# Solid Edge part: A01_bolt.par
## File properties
Author: mokuno
Template: metric.par
Last saved by: edge
Revision: 32
Application: Solid Edge
Material: Copper
File Size: 0
Number of Sheets: 0
Number of Objects: 0
非切断部品: False
文書内容のタイプ: 0
Density: 8906
Accuracy: 0.99
Document Number: MP-101
Revision: 1
Project Name: Trolley Wheel Assembly
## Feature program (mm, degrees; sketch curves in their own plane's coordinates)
sketch for "unnamed RevolvedProtrusion 1" plane through (0, 0, 0) normal (0, -1, 0) x-axis (1, 0, 0)
  line (-50, 0) -> (-50, 10)
  line (-50, 10) -> (-12, 10)
  line (-12, 10) -> (-12, 18)
  line (-12, 18) -> (0, 18)
  line (0, 18) -> (0, 0)
  line (0, 0) -> (-50, 0)
  dimension (linear) = 12
  dimension (linear) = 50
revolve "unnamed RevolvedProtrusion 1" add full turn 360 deg
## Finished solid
Body 1: solid body, 5 faces, 4 edges, 0 vertices.
  Faces by surface: plane 3, cylinder 2
  Edges by curve: circle 4
Bounding box of the edges (mm): 50.000 x 36.000 x 36.000, from (-50, -18, -18) to (0, 18, 18).
Cylindrical faces by radius (mm): R10 x1, R18 x1
Planar faces by outward normal: +x 1, -x 2
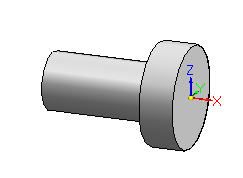
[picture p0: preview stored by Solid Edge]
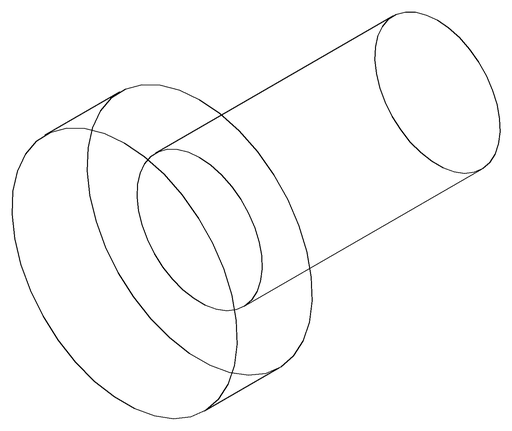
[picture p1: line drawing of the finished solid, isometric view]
